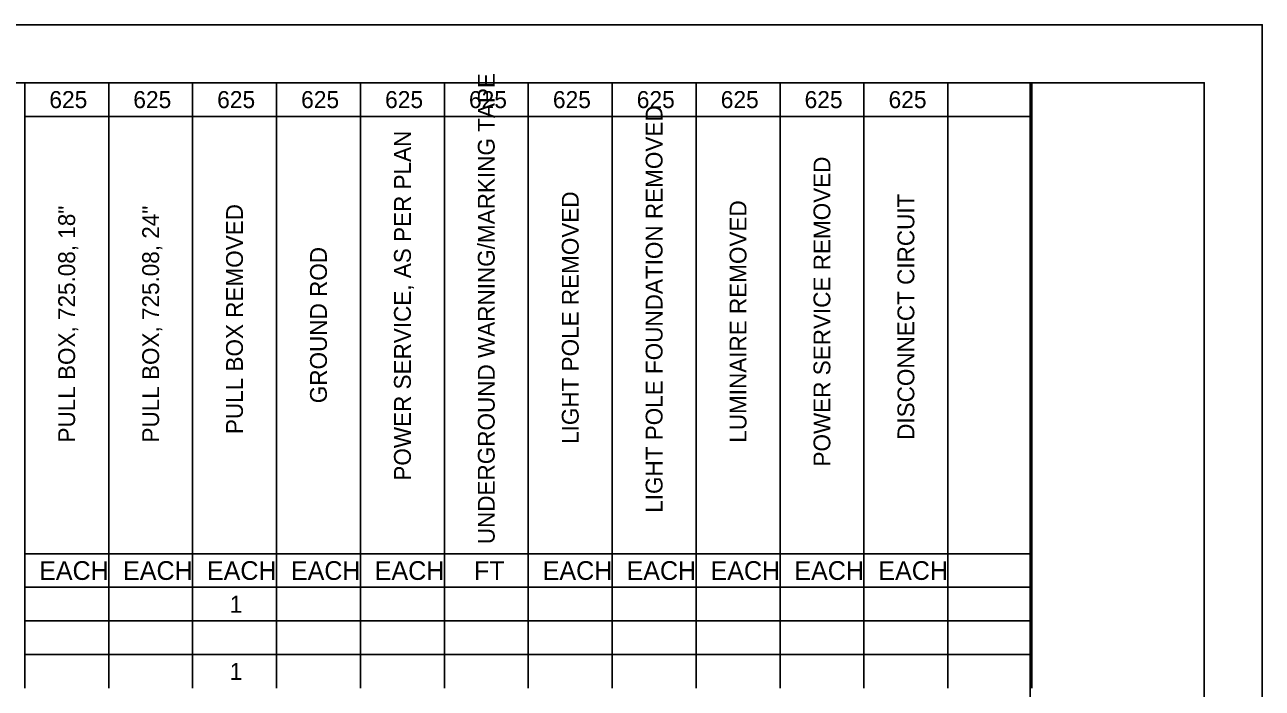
# Model space of a CAD drawing. Extents: x 0 to 34, y 0 to 22.
# Drawn here: x 23.33 to 34, y 16.28 to 22 of the extents above; entities that cross this region are included whole.
import ezdxf

# ---------------------------------------------------------------- set-up
doc = ezdxf.new("R2010")
doc.units = 0
for name, color, linetype in [('Default', 7, 'Continuous'), ('SH_Border', 7, 'Continuous'), ('SH_Cut_Line', 7, 'Continuous')]:
    doc.layers.add(name, color=color, linetype=linetype)

msp = doc.modelspace()

# ---------------------------------------------------------------- linework, layer by layer
at = {"layer": 'Default'}
for p, q in [((23.33, 21.5), (24.054, 21.5)), ((23.33, 21.5), (23.33, 21.21)), ((24.054, 21.5), (26.224, 21.5)), ((24.054, 21.5), (24.054, 21.21)), ((24.777, 21.5), (24.777, 21.21)), ((25.501, 21.5), (25.501, 21.21)), ((26.224, 21.5), (26.948, 21.5)), ((26.224, 21.5), (26.224, 21.21)), ((26.948, 21.5), (27.671, 21.5)), ((26.948, 21.5), (26.948, 21.21)), ((27.671, 21.5), (29.842, 21.5)), ((27.671, 21.5), (27.671, 21.21)), ((28.395, 21.5), (28.395, 21.21)), ((29.119, 21.5), (29.119, 21.21)), ((29.842, 21.5), (30.566, 21.5)), ((29.842, 21.5), (29.842, 21.21)), ((30.566, 21.5), (31.289, 21.5)), ((30.566, 21.5), (30.566, 21.21)), ((31.289, 21.5), (32.013, 21.5)), ((31.289, 21.5), (31.289, 21.21)), ((32.013, 21.5), (32.013, 21.21)), ((23.33, 21.21), (24.054, 21.21)), ((23.33, 21.21), (23.33, 20.92)), ((24.054, 21.21), (26.224, 21.21)), ((24.054, 21.21), (24.054, 20.92)), ((24.777, 21.21), (24.777, 20.92)), ((25.501, 21.21), (25.501, 20.92)), ((26.224, 21.21), (26.948, 21.21)), ((26.224, 21.21), (26.224, 20.92)), ((26.948, 21.21), (27.671, 21.21)), ((26.948, 21.21), (26.948, 20.92)), ((27.671, 21.21), (29.842, 21.21)), ((27.671, 21.21), (27.671, 20.92)), ((28.395, 21.21), (28.395, 20.92)), ((29.119, 21.21), (29.119, 20.92)), ((29.842, 21.21), (30.566, 21.21)), ((29.842, 21.21), (29.842, 20.92)), ((30.566, 21.21), (31.289, 21.21)), ((30.566, 21.21), (30.566, 20.92)), ((31.289, 21.21), (32.013, 21.21)), ((31.289, 21.21), (31.289, 20.92)), ((32.013, 21.21), (32.013, 20.92)), ((23.33, 20.92), (23.33, 20.63)), ((24.054, 20.92), (24.054, 20.63)), ((24.777, 20.92), (24.777, 20.63)), ((25.501, 20.92), (25.501, 20.63)), ((26.224, 20.92), (26.224, 20.63)), ((26.948, 20.92), (26.948, 20.63)), ((27.671, 20.92), (27.671, 20.63)), ((28.395, 20.92), (28.395, 20.63)), ((29.119, 20.92), (29.119, 20.63)), ((29.842, 20.92), (29.842, 20.63)), ((30.566, 20.92), (30.566, 20.63)), ((31.289, 20.92), (31.289, 20.63)), ((32.013, 20.92), (32.013, 20.63)), ((23.33, 20.63), (23.33, 20.339)), ((24.054, 20.63), (24.054, 20.339)), ((24.777, 20.63), (24.777, 20.339)), ((25.501, 20.63), (25.501, 20.339)), ((26.224, 20.63), (26.224, 20.339)), ((26.948, 20.63), (26.948, 20.339)), ((27.671, 20.63), (27.671, 20.339)), ((28.395, 20.63), (28.395, 20.339)), ((29.119, 20.63), (29.119, 20.339)), ((29.842, 20.63), (29.842, 20.339)), ((30.566, 20.63), (30.566, 20.339)), ((31.289, 20.63), (31.289, 20.339)), ((32.013, 20.63), (32.013, 20.339)), ((23.33, 20.339), (23.33, 20.049)), ((24.054, 20.339), (24.054, 20.049)), ((24.777, 20.339), (24.777, 20.049)), ((25.501, 20.339), (25.501, 20.049)), ((26.224, 20.339), (26.224, 20.049)), ((26.948, 20.339), (26.948, 20.049)), ((27.671, 20.339), (27.671, 20.049)), ((28.395, 20.339), (28.395, 20.049)), ((29.119, 20.339), (29.119, 20.049)), ((29.842, 20.339), (29.842, 20.049)), ((30.566, 20.339), (30.566, 20.049)), ((31.289, 20.339), (31.289, 20.049)), ((32.013, 20.339), (32.013, 20.049)), ((23.33, 20.049), (23.33, 19.759)), ((24.054, 20.049), (24.054, 19.759)), ((24.777, 20.049), (24.777, 19.759)), ((25.501, 20.049), (25.501, 19.759)), ((26.224, 20.049), (26.224, 19.759)), ((26.948, 20.049), (26.948, 19.759)), ((27.671, 20.049), (27.671, 19.759)), ((28.395, 20.049), (28.395, 19.759)), ((29.119, 20.049), (29.119, 19.759)), ((29.842, 20.049), (29.842, 19.759)), ((30.566, 20.049), (30.566, 19.759)), ((31.289, 20.049), (31.289, 19.759)), ((32.013, 20.049), (32.013, 19.759)), ((23.33, 19.759), (23.33, 19.469)), ((24.054, 19.759), (24.054, 19.469)), ((24.777, 19.759), (24.777, 19.469)), ((25.501, 19.759), (25.501, 19.469)), ((26.224, 19.759), (26.224, 19.469)), ((26.948, 19.759), (26.948, 19.469)), ((27.671, 19.759), (27.671, 19.469)), ((28.395, 19.759), (28.395, 19.469)), ((29.119, 19.759), (29.119, 19.469)), ((29.842, 19.759), (29.842, 19.469)), ((30.566, 19.759), (30.566, 19.469)), ((31.289, 19.759), (31.289, 19.469)), ((32.013, 19.759), (32.013, 19.469)), ((23.33, 19.469), (23.33, 19.179)), ((24.054, 19.469), (24.054, 19.179)), ((24.777, 19.469), (24.777, 19.179)), ((25.501, 19.469), (25.501, 19.179)), ((26.224, 19.469), (26.224, 19.179)), ((26.948, 19.469), (26.948, 19.179)), ((27.671, 19.469), (27.671, 19.179)), ((28.395, 19.469), (28.395, 19.179)), ((29.119, 19.469), (29.119, 19.179)), ((29.842, 19.469), (29.842, 19.179)), ((30.566, 19.469), (30.566, 19.179)), ((31.289, 19.469), (31.289, 19.179)), ((32.013, 19.469), (32.013, 19.179)), ((23.33, 19.179), (23.33, 18.889)), ((24.054, 19.179), (24.054, 18.889)), ((24.777, 19.179), (24.777, 18.889)), ((25.501, 19.179), (25.501, 18.889)), ((26.224, 19.179), (26.224, 18.889)), ((26.948, 19.179), (26.948, 18.889)), ((27.671, 19.179), (27.671, 18.889)), ((28.395, 19.179), (28.395, 18.889)), ((29.119, 19.179), (29.119, 18.889)), ((29.842, 19.179), (29.842, 18.889)), ((30.566, 19.179), (30.566, 18.889)), ((31.289, 19.179), (31.289, 18.889)), ((32.013, 19.179), (32.013, 18.889)), ((23.33, 18.889), (23.33, 18.599)), ((24.054, 18.889), (24.054, 18.599)), ((24.777, 18.889), (24.777, 18.599)), ((25.501, 18.889), (25.501, 18.599)), ((26.224, 18.889), (26.224, 18.599)), ((26.948, 18.889), (26.948, 18.599)), ((27.671, 18.889), (27.671, 18.599)), ((28.395, 18.889), (28.395, 18.599)), ((29.119, 18.889), (29.119, 18.599)), ((29.842, 18.889), (29.842, 18.599)), ((30.566, 18.889), (30.566, 18.599)), ((31.289, 18.889), (31.289, 18.599)), ((32.013, 18.889), (32.013, 18.599)), ((23.33, 18.599), (23.33, 18.308)), ((24.054, 18.599), (24.054, 18.308)), ((24.777, 18.599), (24.777, 18.308)), ((25.501, 18.599), (25.501, 18.308)), ((26.224, 18.599), (26.224, 18.308)), ((26.948, 18.599), (26.948, 18.308)), ((27.671, 18.599), (27.671, 18.308)), ((28.395, 18.599), (28.395, 18.308)), ((29.119, 18.599), (29.119, 18.308)), ((29.842, 18.599), (29.842, 18.308)), ((30.566, 18.599), (30.566, 18.308)), ((31.289, 18.599), (31.289, 18.308)), ((32.013, 18.599), (32.013, 18.308)), ((23.33, 18.308), (23.33, 18.018)), ((24.054, 18.308), (24.054, 18.018)), ((24.777, 18.308), (24.777, 18.018)), ((25.501, 18.308), (25.501, 18.018)), ((26.224, 18.308), (26.224, 18.018)), ((26.948, 18.308), (26.948, 18.018)), ((27.671, 18.308), (27.671, 18.018)), ((28.395, 18.308), (28.395, 18.018)), ((29.119, 18.308), (29.119, 18.018)), ((29.842, 18.308), (29.842, 18.018)), ((30.566, 18.308), (30.566, 18.018)), ((31.289, 18.308), (31.289, 18.018)), ((32.013, 18.308), (32.013, 18.018)), ((23.33, 18.018), (23.33, 17.728)), ((24.054, 18.018), (24.054, 17.728)), ((24.777, 18.018), (24.777, 17.728)), ((25.501, 18.018), (25.501, 17.728)), ((26.224, 18.018), (26.224, 17.728)), ((26.948, 18.018), (26.948, 17.728)), ((27.671, 18.018), (27.671, 17.728)), ((28.395, 18.018), (28.395, 17.728)), ((29.119, 18.018), (29.119, 17.728)), ((29.842, 18.018), (29.842, 17.728)), ((30.566, 18.018), (30.566, 17.728)), ((31.289, 18.018), (31.289, 17.728)), ((32.013, 18.018), (32.013, 17.728)), ((23.33, 17.728), (23.33, 17.438)), ((24.054, 17.728), (24.054, 17.438)), ((24.777, 17.728), (24.777, 17.438)), ((25.501, 17.728), (25.501, 17.438)), ((26.224, 17.728), (26.224, 17.438)), ((26.948, 17.728), (26.948, 17.438)), ((27.671, 17.728), (27.671, 17.438)), ((28.395, 17.728), (28.395, 17.438)), ((29.119, 17.728), (29.119, 17.438)), ((29.842, 17.728), (29.842, 17.438)), ((30.566, 17.728), (30.566, 17.438)), ((31.289, 17.728), (31.289, 17.438)), ((32.013, 17.728), (32.013, 17.438)), ((23.33, 17.438), (24.054, 17.438)), ((23.33, 17.438), (23.33, 17.148)), ((24.054, 17.438), (26.224, 17.438)), ((24.054, 17.438), (24.054, 17.148)), ((24.777, 17.438), (24.777, 17.148)), ((25.501, 17.438), (25.501, 17.148)), ((26.224, 17.438), (26.948, 17.438)), ((26.224, 17.438), (26.224, 17.148)), ((26.948, 17.438), (27.671, 17.438)), ((26.948, 17.438), (26.948, 17.148)), ((27.671, 17.438), (29.842, 17.438)), ((27.671, 17.438), (27.671, 17.148)), ((28.395, 17.438), (28.395, 17.148)), ((29.119, 17.438), (29.119, 17.148)), ((29.842, 17.438), (30.566, 17.438)), ((29.842, 17.438), (29.842, 17.148)), ((30.566, 17.438), (31.289, 17.438)), ((30.566, 17.438), (30.566, 17.148)), ((31.289, 17.438), (32.013, 17.438)), ((31.289, 17.438), (31.289, 17.148)), ((32.013, 17.438), (32.013, 17.148)), ((23.33, 17.148), (24.054, 17.148)), ((23.33, 17.148), (23.33, 16.858)), ((24.054, 17.148), (26.224, 17.148)), ((24.054, 17.148), (24.054, 16.858)), ((24.777, 17.148), (24.777, 16.858)), ((25.501, 17.148), (25.501, 16.858)), ((26.224, 17.148), (26.948, 17.148)), ((26.224, 17.148), (26.224, 16.858)), ((26.948, 17.148), (27.671, 17.148)), ((26.948, 17.148), (26.948, 16.858)), ((27.671, 17.148), (29.842, 17.148)), ((27.671, 17.148), (27.671, 16.858)), ((28.395, 17.148), (28.395, 16.858)), ((29.119, 17.148), (29.119, 16.858)), ((29.842, 17.148), (30.566, 17.148)), ((29.842, 17.148), (29.842, 16.858)), ((30.566, 17.148), (31.289, 17.148)), ((30.566, 17.148), (30.566, 16.858)), ((31.289, 17.148), (32.013, 17.148)), ((31.289, 17.148), (31.289, 16.858)), ((32.013, 17.148), (32.013, 16.858)), ((23.33, 16.858), (24.054, 16.858)), ((23.33, 16.858), (23.33, 16.568)), ((24.054, 16.858), (26.224, 16.858)), ((24.054, 16.858), (24.054, 16.568)), ((24.777, 16.858), (24.777, 16.568)), ((25.501, 16.858), (25.501, 16.568)), ((26.224, 16.858), (26.948, 16.858)), ((26.224, 16.858), (26.224, 16.568)), ((26.948, 16.858), (27.671, 16.858)), ((26.948, 16.858), (26.948, 16.568)), ((27.671, 16.858), (29.842, 16.858)), ((27.671, 16.858), (27.671, 16.568)), ((28.395, 16.858), (28.395, 16.568)), ((29.119, 16.858), (29.119, 16.568)), ((29.842, 16.858), (30.566, 16.858)), ((29.842, 16.858), (29.842, 16.568)), ((30.566, 16.858), (31.289, 16.858)), ((30.566, 16.858), (30.566, 16.568)), ((31.289, 16.858), (32.013, 16.858)), ((31.289, 16.858), (31.289, 16.568)), ((32.013, 16.858), (32.013, 16.568)), ((23.33, 16.568), (24.054, 16.568)), ((23.33, 16.568), (23.33, 16.278)), ((24.054, 16.568), (26.224, 16.568)), ((24.054, 16.568), (24.054, 16.278)), ((24.777, 16.568), (24.777, 16.278)), ((25.501, 16.568), (25.501, 16.278)), ((26.224, 16.568), (26.948, 16.568)), ((26.224, 16.568), (26.224, 16.278)), ((26.948, 16.568), (27.671, 16.568)), ((26.948, 16.568), (26.948, 16.278)), ((27.671, 16.568), (29.842, 16.568)), ((27.671, 16.568), (27.671, 16.278)), ((28.395, 16.568), (28.395, 16.278)), ((29.119, 16.568), (29.119, 16.278)), ((29.842, 16.568), (30.566, 16.568)), ((29.842, 16.568), (29.842, 16.278)), ((30.566, 16.568), (31.289, 16.568)), ((30.566, 16.568), (30.566, 16.278)), ((31.289, 16.568), (32.013, 16.568)), ((31.289, 16.568), (31.289, 16.278)), ((32.013, 16.568), (32.013, 16.278))]:
    msp.add_line(p, q, dxfattribs=at)
at = {"layer": 'SH_Border'}
msp.add_line((32, 0.5), (32, 21.5), dxfattribs=at)
msp.add_lwpolyline([(1.5, 21.5), (33.5, 21.5), (33.5, 0.5), (1.5, 0.5)], close=True, dxfattribs=at)
at = {"layer": 'SH_Cut_Line'}
msp.add_lwpolyline([(0, 0), (34, 0), (34, 22), (0, 22)], close=True, dxfattribs=at)

# ---------------------------------------------------------------- texts
at = {"layer": 'Default'}
for s, height, p in [('UNDERGROUND WARNING/MARKING TAPE', 0.14506, (27.382, 17.52)), ('LIGHT POLE FOUNDATION REMOVED', 0.14506, (28.829, 17.791)), ('POWER SERVICE, AS PER PLAN', 0.14506, (26.659, 18.068)), ('POWER SERVICE REMOVED', 0.14506, (30.276, 18.19)), ('LIGHT POLE REMOVED', 0.14506, (28.106, 18.385)), ('DISCONNECT CIRCUIT', 0.14506, (31, 18.42)), ('PULL BOX, 725.08, 18"', 0.14506, (23.764, 18.397)), ('PULL BOX, 725.08, 24"', 0.14506, (24.488, 18.397)), ('PULL BOX REMOVED', 0.14506, (25.211, 18.47)), ('LUMINAIRE REMOVED', 0.14506, (29.553, 18.395)), ('GROUND ROD', 0.1451, (25.935, 18.736))]:
    msp.add_text(s, height=height, rotation=90, dxfattribs=at).set_placement(p)
for s, height, p in [('625', 0.1468, (23.542, 21.281)), ('625', 0.1468, (24.266, 21.281)), ('625', 0.1468, (24.989, 21.281)), ('625', 0.1468, (25.713, 21.281)), ('625', 0.1468, (26.437, 21.281)), ('625', 0.1468, (27.16, 21.281)), ('625', 0.1468, (27.884, 21.281)), ('625', 0.1468, (28.607, 21.281)), ('625', 0.1468, (29.331, 21.281)), ('625', 0.1468, (30.054, 21.281)), ('625', 0.1468, (30.778, 21.281)), ('EACH', 0.1615, (23.454, 17.212)), ('EACH', 0.1615, (24.178, 17.212)), ('EACH', 0.1615, (24.901, 17.212)), ('EACH', 0.1615, (25.625, 17.212)), ('EACH', 0.1615, (26.348, 17.212)), ('FT', 0.1615, (27.204, 17.212)), ('EACH', 0.1615, (27.796, 17.212)), ('EACH', 0.1615, (28.519, 17.212)), ('EACH', 0.1615, (29.243, 17.212)), ('EACH', 0.1615, (29.966, 17.212)), ('EACH', 0.1615, (30.69, 17.212)), ('1', 0.147, (25.097, 16.929)), ('1', 0.147, (25.097, 16.349))]:
    msp.add_text(s, height=height, dxfattribs=at).set_placement(p)

doc.saveas('drawing.dxf')
